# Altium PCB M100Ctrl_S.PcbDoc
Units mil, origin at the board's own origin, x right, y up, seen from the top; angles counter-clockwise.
Board outline 2362.2 x 2007.87 mil, 2 copper layers (Top Layer, Bottom Layer); 93 components, 74 nets, 370 pads, 105 vias.
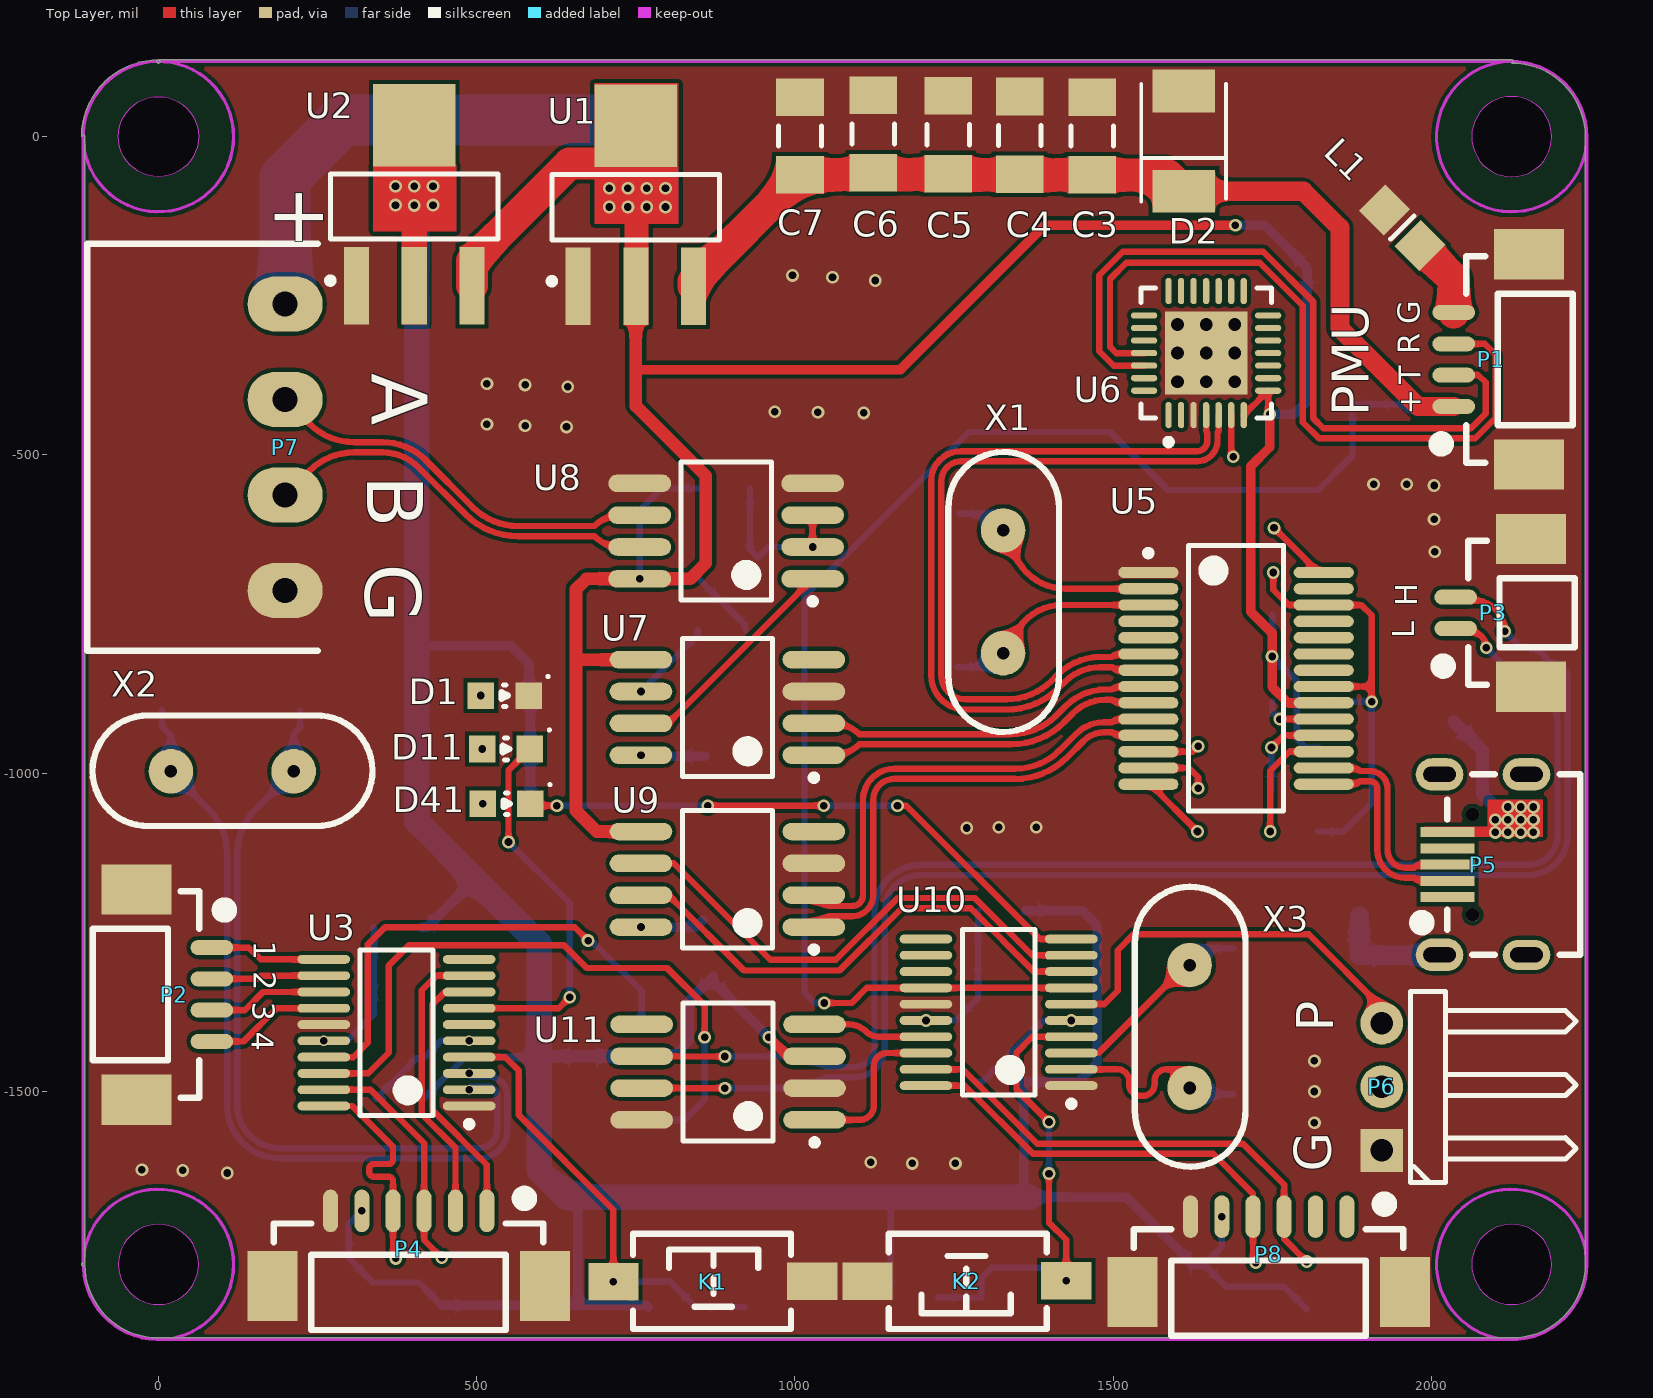
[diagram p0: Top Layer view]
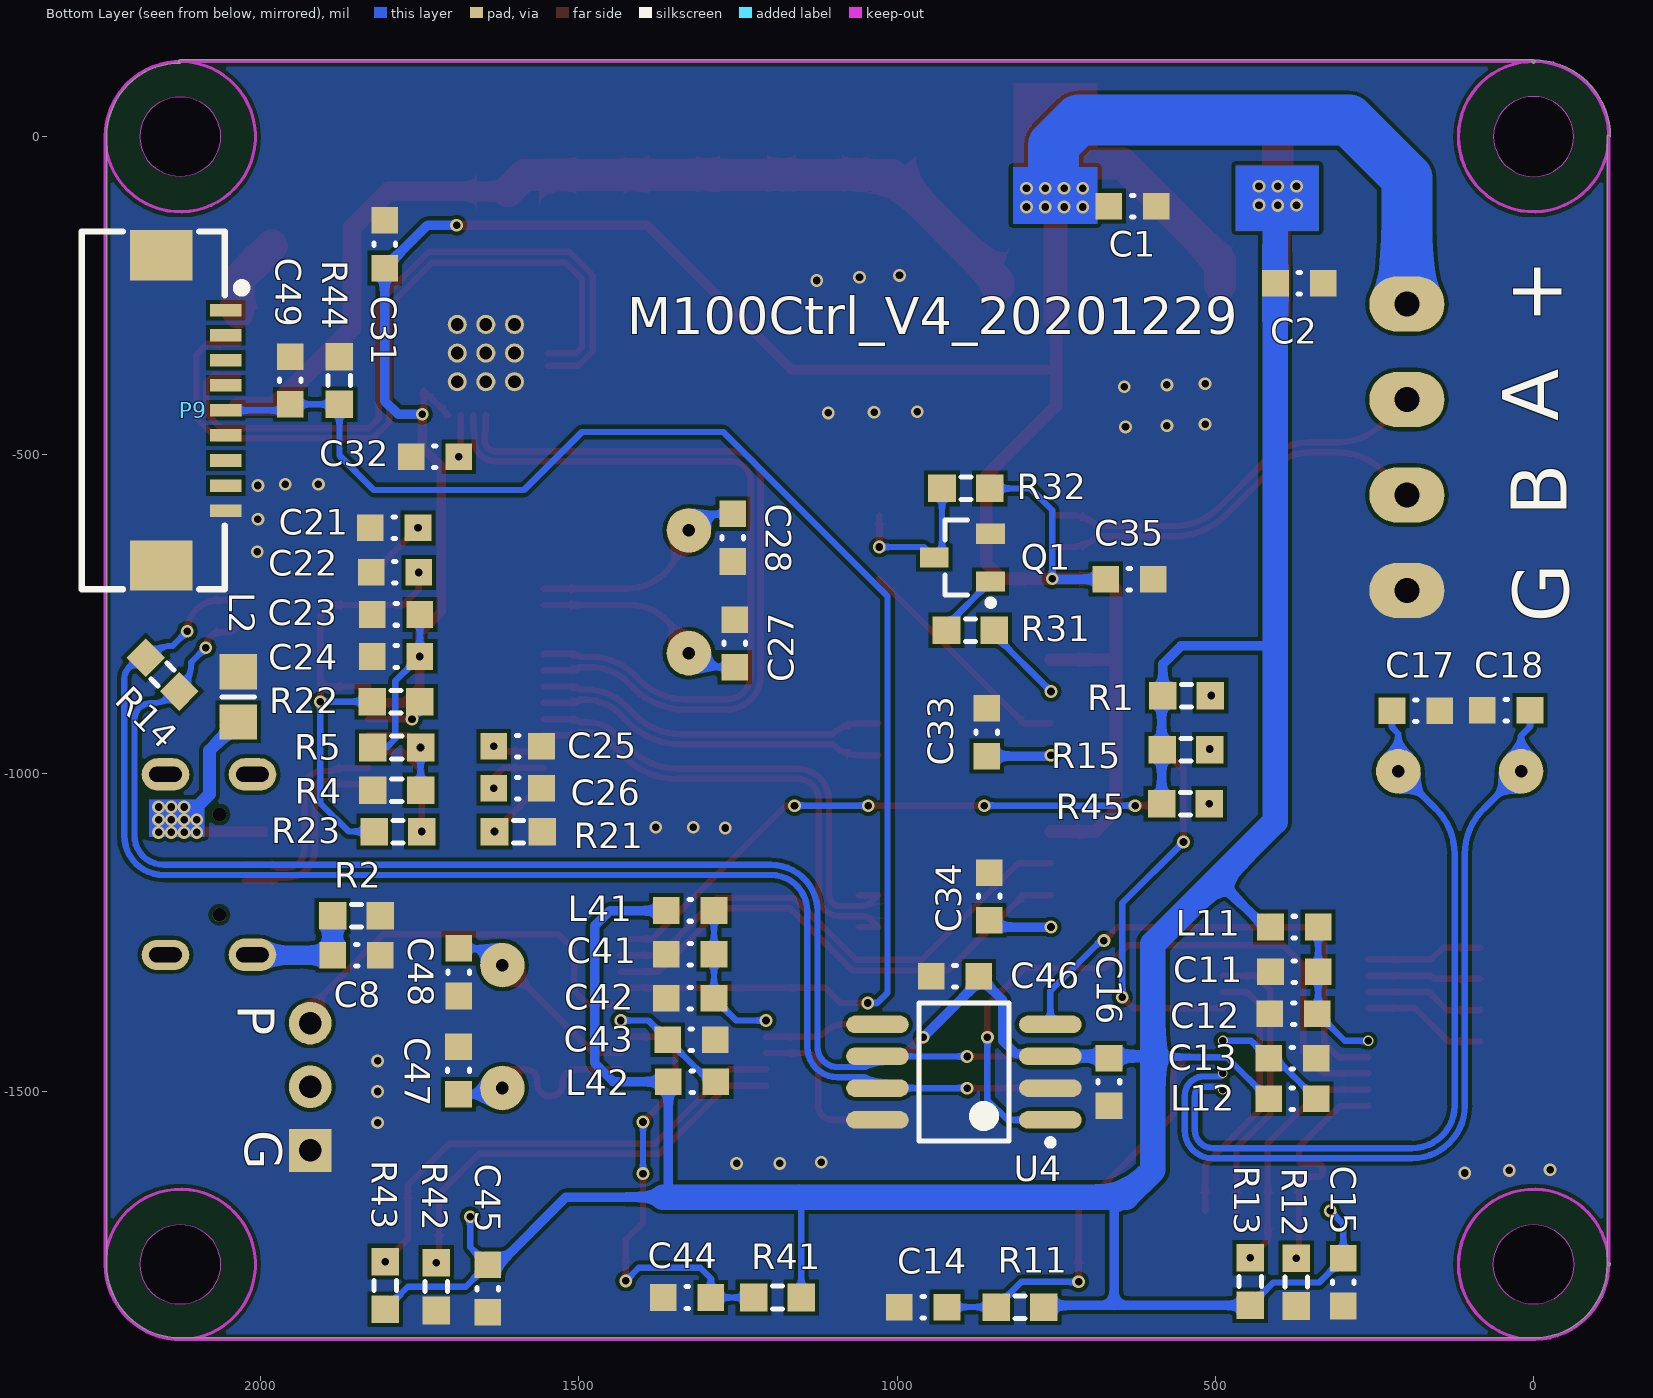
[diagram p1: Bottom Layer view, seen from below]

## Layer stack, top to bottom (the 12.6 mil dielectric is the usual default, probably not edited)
Top Solder: solder mask 0.4, Solder Resist, Dk 3.5
Top Layer: signal copper 1.4
Dielectric 1: dielectric 12.6, FR-4, Dk 4.8
Bottom Layer: signal copper 1.4
Bottom Solder: solder mask 0.4, Solder Resist, Dk 3.5

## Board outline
-120.63,-1771.68 cw(c0,-1771.65) -120.63,-1771.65 cw(c-118.11,-1771.65) -120.63,-1771.65 cw(c-118.11,-1771.65) -115.6,-1771.63 cw(c-118.11,-1771.65) -115.6,-1771.65 ccw(c0,-1771.65) -0.02,-1887.25 cw(c0,-1889.76) 0,-1887.25 2125.98,-1887.25 cw(c2125.98,-1889.76) 2126.01,-1887.25 ccw(c2125.98,-1771.65) 2241.58,-1771.65 2241.58,0 ccw(c2125.98,0) 2126.01,115.6 ccw(c2125.98,118.11) 2128.5,118.11 ccw(c2125.98,118.11) 2125.98,120.63 0,120.63 ccw(c0,118.11) -0.02,115.6 cw(c0,0) 0,115.6 ccw(c0,118.11) 2.52,118.11 ccw(c0,118.11) 0.02,120.63 ccw(c0,118.11) 0,120.63 ccw(c0,0) -120.63,0.02 cw(c-118.11,0) -115.6,0 -115.6,-1771.65 cw(c-118.11,-1771.65)
cut-out: 0,-62.99 cw(c0,0) -62.99,0 cw(c0,0) 0,62.99 cw(c0,0) 62.99,0 cw(c0,0)
cut-out: -62.99,-1771.65 ccw(c0,-1771.65) 0,-1834.65 ccw(c0,-1771.65) 62.99,-1771.65 ccw(c0,-1771.65) 0,-1708.66 ccw(c0,-1771.65)
cut-out: 2062.99,-1771.65 ccw(c2125.98,-1771.65) 2125.98,-1834.65 ccw(c2125.98,-1771.65) 2188.98,-1771.65 ccw(c2125.98,-1771.65) 2125.98,-1708.66 ccw(c2125.98,-1771.65)
cut-out: 2062.99,0 ccw(c2125.98,0) 2125.98,-62.99 ccw(c2125.98,0) 2188.98,0 ccw(c2125.98,0) 2125.98,62.99 ccw(c2125.98,0)

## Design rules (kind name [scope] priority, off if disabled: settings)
Clearance 24V [InNetClass('24V')] p1: gap=12
Clearance [All] p2: gap=6
ComponentClearance [All] p1: gap=0 collisioncheckmode=3 verticalgap=0 showdistances=FALSE
DiffPairsRouting [All] p1: maxlimit=10 minlimit=6 mostfreqgap=6 toplayer_minwidth=10 toplayer_maxwidth=10 toplayer_prefwidth=10 bottomlayer_minwidth=10 bottomlayer_maxwidth=10 bottomlayer_prefwidth=10 maxuncoupledlength=500
HoleSize [All] p1: absolutevalues=TRUE maxlimit=10000 minlimit=12 maxpercent=80.000 minpercent=20.000
HoleToHoleClearance [All] p1: gap=6 allowstackedmicrovias=TRUE
MinimumSolderMaskSliver [All] p1: minsoldermaskwidth=0
PolygonConnect VIA [OnLayer('Multi-Layer')] p1: connectstyle=Direct reliefconductorwidth=10 reliefentries=4 polygonreliefangle="90 Angle" airgapwidth=10
PolygonConnect [All] p2: connectstyle=Direct reliefconductorwidth=10 reliefentries=4 polygonreliefangle="90 Angle" airgapwidth=10
RoutingVias [All] p1: holewidth=12 width=15 viastyle="Through Hole" minholewidth=12 minwidth=12 maxholewidth=200 maxwidth=200
SilkToBoardRegionClearance [All] p1 off:
SilkToSilkClearance [All] p1: silktosilkclearance=0
SilkToSolderMaskClearance [IsPad] p1: minsilkscreentomaskgap=0 clearancetoexposedcopper=TRUE
SolderMaskExpansion [All] p1: expansion=4
Width [All] p1: maxlimit=10000 minlimit=6 preferedwidth=10
22 further rules are at their usual default settings.

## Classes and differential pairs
component class uart: C31 C32 C33 C34 C35 P6 P7 Q1 R31 R32 U6 U7 U8 U9
component class usbhub: C21 C22 C23 C24 C25 C26 C27 C28 L2 P5 R4 R5 R21 R22 R23 U5 X1
component class PWM2CAN: C11 C12 C13 C14 C15 C16 C17 C18 D11 K1 L11 L12 P2 P3 P4 R11 R12 R13 R14 R15 U3 U4 X2
component class power: C1 C2 C3 C4 C5 C6 C7 C8 D1 D2 L1 P1 R1 R2 U1 U2
component class rpm: C41 C42 C43 C44 C45 C46 C47 C48 C49 D41 K2 L41 L42 P8 P9 R41 R42 R43 R44 R45 U10 U11 X3
differential pair OSC_M1: +OSC_M1_P -OSC_M1_N
differential pair OSC_M2: +OSC_M2_P -OSC_M2_N
differential pair 485: +485_P -485_N
differential pair USB_MASTER: +USB_MASTER_P -USB_MASTER_N
differential pair USB4: +USB4_P -USB4_N
differential pair USB3: +USB3_P -USB3_N
differential pair USB2: +USB2_P -USB2_N
differential pair USB1: +USB1_P -USB1_N
differential pair OSC_HUB: +OSC_HUB_P -OSC_HUB_N
differential pair CAN: +CAN_P -CAN_N

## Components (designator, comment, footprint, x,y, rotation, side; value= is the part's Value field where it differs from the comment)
C1 "226" C0603/1608 630,-109 r0 bottom
C2 "226" C0603/1608 368,-230 r0 bottom
C3 "226" C1206/3216 1466.89,1 r270 top
C4 "226" C1206/3216 1352.89,2 r270 top
C5 "226" C1206/3216 1240.89,3 r270 top
C6 "226" C1206/3216 1122.89,4 r270 top
C7 "226" C1206/3216 1007.89,1 r270 top
C8 "104" C0603/1608 1849,-1286 r0 bottom
C11 "104" C0603/1608 375.89,-1311.65 r180 bottom
C12 "106" C0603/1608 376.89,-1377.65 r180 bottom
C13 "104" C0603/1608 378.89,-1447.65 r0 bottom
C14 "105" C0603/1608 958.89,-1838.65 r180 bottom
C15 "104" C0603/1608 298.89,-1799.65 r270 bottom
C16 "104" C0603/1608 667,-1485 r270 bottom
C17 "20pF" C0603/1608 185,-902 r180 bottom
C18 "20pF" C0603/1608 43,-901 r0 bottom
C21 "104" C0603/1608 1789.89,-614.65 r180 bottom
C22 "106" C0603/1608 1788.89,-684.65 r180 bottom
C23 "106" C0603/1608 1786.89,-750.65 r180 bottom
C24 "104" C0603/1608 1786.89,-816.65 r0 bottom
C25 "106" C0603/1608 1595.89,-957.65 r180 bottom
C26 "104" C0603/1608 1595.89,-1023.65 r180 bottom
C27 "20pF" C0603/1608 1254.89,-796 r90 bottom
C28 "20pF" C0603/1608 1257.89,-630 r270 bottom
C31 "105" C0603/1608 1804.89,-169 r270 bottom
C32 "104" C0603/1608 1725.89,-503 r180 bottom
C33 "104" C0603/1608 858.89,-935.65 r90 bottom
C34 "104" C0603/1608 854.89,-1193.65 r90 bottom
C35 "104" C0603/1608 634.89,-695 r0 bottom
C41 "104" C0603/1608 1324.89,-1284.65 r180 bottom
C42 "106" C0603/1608 1324.89,-1353.65 r180 bottom
C43 "104" C0603/1608 1322.89,-1418.65 r0 bottom
C44 "105" C0603/1608 1329.89,-1823.65 r180 bottom
C45 "104" C0603/1608 1642.89,-1809.65 r270 bottom
C46 "104" C0603/1608 908.89,-1319 r0 bottom
C47 "20pF" C0603/1608 1688.89,-1467 r90 bottom
C48 "20pF" C0603/1608 1688.34,-1312.6 r270 bottom
C49 "22nF" C0603/1608 1952.89,-383 r90 bottom
D1 "LED-红色" LED0603-蓝色 544,-878 r0 top
D2 "SMAJ11CA" DO-214AC/SMA 1611,-7 r270 top
D11 "LED-绿色" LED0603-蓝色 546,-962 r0 top
D41 "LED-蓝色" LED0603-蓝色 547,-1048 r0 top
K1 "KEY" 按键（2脚） 870.89,-1798.65 r0 top
K2 "KEY" 按键（2脚） 1270,-1798 r180 top
L1 "UPZ2012E221" L0805/2012 1954,-143 r315 top
L2 "UPZ2012E221" L0805/2012 2035,-880 r270 bottom
L11 "UPZ1608E101" L0603/1608 375.89,-1241.65 r180 bottom
L12 "UPZ1608E101" L0603/1608 378.89,-1511.65 r180 bottom
L41 "UPZ1608E101" L0603/1608 1324.89,-1215.65 r180 bottom
L42 "UPZ1608E101" L0603/1608 1321.89,-1484.65 r180 bottom
P1 "GH1.25-4P-N3API" GH1.25-4P（卧贴） 2034.89,-423.65 r270 top
P2 "GH1.25-4P" GH1.25-4P（卧贴） 83.89,-1274 r90 top
P3 "GH1.25-2P-CAN" GH1.25-2P（卧贴） 2037.89,-772.65 r270 top
P4 "GH1.25-6P-SW\UART\3.3V" GH1.25-6P（立贴） 515.89,-1687.65 r180 top
P5 "Micro USB" "Micro USB" 2080.89,-1143.65 r90 top
P6 "Header-3P" HDR2.54-WI-3P 1921.89,-1492.65 r90 top
P7 "KF-4P" KF3.81-4P（卧式） 199,-488 r270 top
P8 "GH1.25-6P-SW\UART\3.3V" GH1.25-6P（立贴） 1866.89,-1696.65 r180 top
P9 "SH1.0-9P-Realsense" FPC1.0-2H-WS-9P 2155.89,-430 r270 bottom
Q1 "PMBT3904" SOT-23-3 852.89,-698.65 r0 bottom
R1 "10k" R0603/1608 545,-878 r0 bottom
R2 "10k" R0603/1608 1849.34,-1224.27 r0 bottom
R4 "100k" R0603/1608 1785.89,-1026.65 r0 bottom
R5 "47k" R0603/1608 1785.89,-959.65 r180 bottom
R11 "1k" R0603/1608 806.89,-1839 r0 bottom
R12 "10k" R0603/1608 372.89,-1799.65 r90 bottom
R13 "10k" R0603/1608 444.89,-1798.65 r90 bottom
R14 "120R" R0603/1608 2153.89,-845 r45 bottom
R15 "10k" R0603/1608 546,-963 r0 bottom
R21 "2k7" R0603/1608 1594.89,-1091.65 r0 bottom
R22 "100k" R0603/1608 1786.89,-887.65 r180 bottom
R23 "100k" R0603/1608 1783.89,-1091.65 r180 bottom
R31 "4k7" R0603/1608 884.89,-775.65 r0 bottom
R32 "4k7" R0603/1608 891.89,-552.65 r0 bottom
R41 "1k" R0603/1608 1187.89,-1823.65 r0 bottom
R42 "10k" R0603/1608 1723.89,-1806.65 r90 bottom
R43 "10k" R0603/1608 1803.89,-1804.65 r90 bottom
R44 "20k" R0603/1608 1875.89,-383 r270 bottom
R45 "10k" R0603/1608 547,-1048 r0 bottom
U1 "AMS1117-5V" SOT-223 749.89,-109 r90 top
U2 "AMS1117-3.3V" SOT-223 401.89,-108 r90 top
U3 "STM32F042F4Px" TSSOP20 373.89,-1407.65 r180 top
U4 "SN65HVD230" SOP-8 894.89,-1469.65 r0 bottom
U5 "FE1.1S USB2.0 HUB" SOP65P780-28M 1692.89,-851 r0 top
U6 "CP2102" QFN50P500X500-28VAM 1645.89,-340 r90 top
U7 "CH340N" SOP-8 893.89,-896.65 r180 top
U8 "MAX485" SOP-8 891.89,-619.65 r180 top
U9 "CH340N" SOP-8 893.89,-1166.65 r180 top
U10 "STM32F042F4Px" TSSOP20 1319.89,-1375.65 r180 top
U11 "SN65HVD230" SOP-8 894.89,-1469.65 r180 top
X1 "XTAL" XTAL-49S 1327,-715 r270 top
X2 "XTAL" XTAL-49S 116,-997 r0 top
X3 "XTAL" XTAL-49S 1620,-1398 r270 top

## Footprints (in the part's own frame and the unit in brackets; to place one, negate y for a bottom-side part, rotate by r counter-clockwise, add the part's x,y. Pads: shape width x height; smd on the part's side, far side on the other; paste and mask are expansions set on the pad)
C0603/1608 [mm] "0603/1608贴片陶瓷电容"
  rect 1.06x1.06 smd: 1(-0.95,0) 2(0.95,0)
  silkscreen extent -0.05,-0.43 0.05,0.43, body extent -1.29,-0.48 1.31,0.53, height 0.95
C1206/3216 [mm] "1206/3216贴片陶瓷电容"
  rect 1.5x1.9 smd: 1(-1.55,0) 2(1.55,0)
  silkscreen extent -0.4,-0.85 0.4,0.85, body extent -2.18,-0.92 2.02,0.88, height 0.95
DO-214AC/SMA [mm]
  rect 1.7x2.5 smd: 1(-2,0) 2(2,0)
  silkscreen extent -2.29,-1.7 2.41,1.68, body extent -2.85,-1.25 2.85,1.25, height 1.9
FPC1.0-2H-WS-9P [mm] "翻盖FPC，脚距1mm，不含脚（长13.9mm，宽5.2mm，高1.96mm）"
  rect 2x2.5 smd: 0(-6.19,0) 0(6.19,0)
  rect 0.5x1.25 smd: 1(-4,2.575) 2(-3,2.575) 3(-2,2.575) 4(-1,2.575) 5(0,2.575) 6(1,2.575) 7(2,2.575) 8(3,2.575) 9(4,2.575)
  silkscreen extent -7.14,-3.18 7.14,3.31, body extent -6.95,-3.15 6.95,2.85, height 2
GH1.25-2P（卧贴） [mm]
  rect 2x2.8 smd: 0(-3.575,3) 0(2.325,3)
  oval 0.6x1.7 smd: 1(0,0) 2(-1.25,0)
  silkscreen extent -3.5,-0.75 2.25,4.75, body extent -4.45,-0.25 3.2,4.95, height 3.5
GH1.25-4P（卧贴） [mm]
  rect 2x2.8 smd: 0(-6.07,3) 0(2.325,3)
  oval 0.6x1.7 smd: 1(0,0) 2(-1.245,0) 3(-2.495,0) 4(-3.745,0)
  silkscreen extent -5.99,-0.75 2.26,4.75, body extent -6.95,-0.25 3.2,4.95, height 3.5
GH1.25-6P（立贴） [mm]
  rect 2x2.8 smd: 0(-2.325,3) 0(8.559,3)
  oval 0.6x1.7 smd: 1(0,0) 2(1.25,0) 3(2.5,0) 4(3.745,0) 5(4.989,0) 6(6.234,0)
  silkscreen extent -2.25,-0.75 8.5,4.75, body extent -3.21,0.15 9.44,4.35, height 4.7
HDR2.54-WI-3P [mm] "弯脚排针，3脚"
  rect 1.7x1.7 hole 0.9: 1(-2.54,0)
  round 1.7 hole 0.9: 2(0,0) 3(2.54,0)
  silkscreen extent -3.81,-7.76 3.81,-1.14, body extent -3.81,-7.77 3.81,1.27, height 4.85
KF3.81-4P（卧式） [mm]
  oval 2.2x3 hole 1: 1(-5.715,0) 2(-1.905,0) 3(1.905,0) 4(5.715,0)
  silkscreen extent -8.12,-7.9 8.12,1.3
L0603/1608 [mm] "0603/1608贴片磁珠"
  rect 1.06x1.06 smd: 1(-0.95,0) 2(0.95,0)
  silkscreen extent -0.05,-0.43 0.05,0.43, body extent -0.9,-0.5 0.9,0.5, height 1
L0805/2012 [mm] "0805/2012贴片磁珠"
  rect 1.4x1.5 smd: 1(-1,0) 2(1,0)
  silkscreen extent 0,-0.65 0,0.65, body extent -1.07,-0.7 1.08,0.7, height 0.7
LED0603-蓝色 [mm]
  rect 1.06x1.06 smd: 1(-0.95,0) 2(0.95,0)
  silkscreen extent -0.13,-0.43 1.78,0.81, body extent -0.8,-0.4 0.8,0.4, height 0.35
"Micro USB" [mm]
  oval 1.2x1.9 hole 0.6 slot 1.3 at 90 deg: 0(-3.6,-1.735)
  oval 1.3x1.9 hole 0.6 slot 1.3 at 90 deg: 0(-3.6,1.735) 0(3.6,-1.735) 0(3.6,1.735)
  rect 0.4x2.15 smd: 1(-1.3,1.425) 2(-0.65,1.425) 3(0,1.425) 4(0.65,1.425) 5(1.3,1.425)
  round 0.55 hole 0.55: FX(-2,0.415) FX(2,0.415)
  silkscreen extent -3.6,-3.88 3.6,2.69
QFN50P500X500-28VAM [mm] "28-Pin Plastic Quad Flat No-Lead 0.5 mm Pitch"
  oval 1.05x0.25 smd: 1(-2.475,1.5) 2(-2.475,1) 3(-2.475,0.5) 4(-2.475,0) 5(-2.475,-0.5) 6(-2.475,-1) 7(-2.475,-1.5) 15(2.475,-1.5) 16(2.475,-1) 17(2.475,-0.5) 18(2.475,0) 19(2.475,0.5) 20(2.475,1) 21(2.475,1.5)
  oval 0.25x1.05 smd: 8(-1.5,-2.475) 9(-1,-2.475) 10(-0.5,-2.475) 11(0,-2.475) 12(0.5,-2.475) 13(1,-2.475) 14(1.5,-2.475) 22(1.5,2.475) 23(1,2.475) 24(0.5,2.475) 25(0,2.475) 26(-0.5,2.475) 27(-1,2.475) 28(-1.5,2.475)
  round 0.762 hole 0.508: 29(-1.143,-1.143) 29(-1.143,0) 29(-1.143,1.143) 29(0,1.143) 29(0,0) 29(0,-1.143) 29(1.143,-1.143) 29(1.143,0) 29(1.143,1.143)
  rect 3.3x3.3 smd: 29(0,0)
  silkscreen extent -3.67,-2.6 2.6,2.6, body extent -2.58,-2.58 2.58,2.58, height 1
R0603/1608 [mm] "0603/1608贴片电阻"
  rect 1.1x1.1 smd: 1(-0.95,0) 2(0.95,0)
  silkscreen extent -0.2,-0.45 0.2,0.45, body extent -0.8,-0.4 0.8,0.4, height 0.45
SOP65P780-28M [mm]
  oval 2.4x0.45 smd: 1(-3.5,4.225) 2(-3.5,3.575) 3(-3.5,2.925) 4(-3.5,2.275) 5(-3.5,1.625) 6(-3.5,0.975) 7(-3.5,0.325) 8(-3.5,-0.325) 9(-3.5,-0.975) 10(-3.5,-1.625) 11(-3.5,-2.275) 12(-3.5,-2.925) 13(-3.5,-3.575) 14(-3.5,-4.225) 15(3.5,-4.225) 16(3.5,-3.575) 17(3.5,-2.925) 18(3.5,-2.275) 19(3.5,-1.625) 20(3.5,-0.975) 21(3.5,-0.325) 22(3.5,0.325) 23(3.5,0.975) 24(3.5,1.625) 25(3.5,2.275) 26(3.5,2.925) 27(3.5,3.575) 28(3.5,4.225)
  silkscreen extent -3.62,-5.3 1.9,5.3, body extent -2.7,-5.3 2.7,5.3, height 2
SOP-8 [mm]
  oval 2.5x0.7 smd: 1(-3.45,1.905) 2(-3.45,0.635) 3(-3.45,-0.635) 4(-3.45,-1.905) 5(3.45,-1.905) 6(3.45,-0.635) 7(3.45,0.635) 8(3.45,1.905)
  silkscreen extent -3.57,-2.75 1.8,2.93, body extent -2.73,-2.75 2.73,2.75, height 2.13
SOT-23-3 [mm]
  rect 1.15x0.8 smd: 1(0,0) 2(0,-1.9) 3(2.25,-0.95)
  silkscreen extent -0.12,-2.45 1.83,0.97, body extent -0.38,-2.5 2.62,0.6, height 1.1
SOT-223 [mm]
  rect 3.1x1 smd: 1(-3.2,2.3) 2(-3.2,0) 3(-3.2,-2.3)
  rect 3.3x3.3 smd: 4(3.2,0)
  silkscreen extent -3.12,-3.35 1.25,3.47, body extent -1.9,-3.35 1.8,3.35, height 1.8
TSSOP20 [mm]
  oval 2.1x0.35 smd: 1(-2.9,2.925) 2(-2.9,2.275) 3(-2.9,1.625) 4(-2.9,0.975) 5(-2.9,0.325) 6(-2.9,-0.325) 7(-2.9,-0.975) 8(-2.9,-1.625) 9(-2.9,-2.275) 10(-2.9,-2.925) 11(2.9,-2.925) 12(2.9,-2.275) 13(2.9,-1.625) 14(2.9,-0.975) 15(2.9,-0.325) 16(2.9,0.325) 17(2.9,0.975) 18(2.9,1.625) 19(2.9,2.275) 20(2.9,2.925)
  silkscreen extent -3.03,-3.3 1.45,3.77, body extent -2.25,-3.3 2.25,3.3, height 1.2
XTAL-49S [mil]
  round 70 hole 20: 1(-96.5,0) 2(96.5,0)
  silkscreen extent -220,-86 220,88, body extent -224,-92 223,92, height 142
按键（2脚） [mm]
  rect 2x1.5 smd: 1(-3.966,-0.01) 2(3.966,0.01)
  silkscreen extent -3.18,-1.89 3.12,1.91, body extent -3.97,-1.87 4.03,1.63, height 2.59

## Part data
C1 C2 C3 C4 C5 C6 C7 C8 C11 C12 C13 C14 C15 C16 C17 C18 C21 C22 C23 C24 C25 C26 C27 C28 C31 C32 C33 C34 C35 C41 C42 C43 C44 C45 C46 C47 C48 C49: library part 陶瓷电容, "陶瓷电容"
D1 D11 D41: library part LED, "发光二极管"
D2: library part 瞬态抑制二极管, "瞬态抑制二极管"
K1 K2: library part 按键（2脚）, "按键-2脚贴片"
L1 L2 L11 L12 L41 L42: library part 磁珠, "贴片磁珠"
P2: "GH1.25-4P-CAN\5V"
P5: "Micro USB底座"
Q1: library part NPN, "NPN三极管"
R1 R2 R4 R5 R11 R12 R13 R14 R15 R21 R22 R23 R31 R32 R41 R42 R43 R44 R45: library part 电阻, "电阻"
U1 U2: library part AMS1117, "AMS1117低压差线性稳压器"
U4 U11: "CAN收发芯片"
U7 U9: "USB-TTL转换芯片"
X1 X2 X3: library part 晶振, "晶振"

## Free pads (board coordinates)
  round 216.54 on Top Solder: ""(0,-1771.65) ""(0,0) ""(2125.98,-1771.65) ""(2125.98,0)
  round 216.54 on Bottom Solder: ""(0,-1771.65) ""(0,0) ""(2125.98,-1771.65) ""(2125.98,0)

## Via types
v1: diameter 20, hole 12, Top Layer to Bottom Layer, tented both sides, 101 vias
v2: diameter 15, hole 12, Top Layer to Bottom Layer, tented both sides, 2 vias
v3: diameter 16, hole 12, Top Layer to Bottom Layer, tented both sides, 2 vias

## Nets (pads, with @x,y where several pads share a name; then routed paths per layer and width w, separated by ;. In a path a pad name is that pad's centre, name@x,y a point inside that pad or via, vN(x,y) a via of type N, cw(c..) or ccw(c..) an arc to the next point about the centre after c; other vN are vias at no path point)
485_N: P7.3 U8.7 | length 631.2
  Top Layer w10: P7.3 236.71,-525.29 cw(c307.42,-596) 307.42,-496 352,-496 cw(c352,-575.67) 408.33,-519.33 482.68,-593.68 ccw(c564.7,-511.65) 564.7,-627.65 684.85,-627.65 ccw(c725.89,-586.61) 725.89,-644.65 U8.7
485_P: P7.2 U8.6 | length 631.2
  Top Layer w10: P7.2 236.71,-450.71 ccw(c307.42,-380) 307.42,-480 352,-480 cw(c352,-575.67) 419.65,-508.02 493.99,-582.36 ccw(c564.7,-511.65) 564.7,-611.65 684.85,-611.65 cw(c725.89,-652.7) 725.89,-594.65 U8.6
CAN_N: P3.1 R14.1 U4.6 U11.6 | length 2163.7
  Top Layer w10: U11.6 813.28,-1444.65 813.62,-1445 v1(889.89,-1445) ; P3.1 ccw(c2049.96,-760.58) 2049.96,-777.65 2060.54,-777.65 cw(c2060.54,-803) v1(2085.89,-803)
  Bottom Layer w10: v1(889.89,-1445) 976.16,-1445 976.5,-1444.65 U4.6 1043.35,-1457.29 ccw(c1053.89,-1446.75) 1053.89,-1461.65 1093.24,-1461.65 ccw(c1093.24,-1430) 1124.89,-1430 1124.89,-1217 cw(c1197.89,-1217) 1197.89,-1144 2151.89,-1144 ccw(c2151.89,-1098) 2197.89,-1098 2197.89,-915.24 ccw(c2172.94,-915.24) 2172.94,-890.29 cw(c2172.94,-825.95) R14.1 cw(c2172.94,-825.95) 2108.6,-825.95 2108.6,-825.71 v1(2085.89,-803)
CAN_P: P3.2 R14.2 U4.7 U11.7 | length 2254.5
  Top Layer w10: U11.7 889.54,-1494.65 v1(889.89,-1495) ; P3.2 ccw(c2049.96,-711.37) 2049.96,-728.44 2066.33,-728.44 cw(c2066.33,-777) v1(2114.89,-777)
  Bottom Layer w10: v1(889.89,-1495) 890.24,-1494.65 U4.7 1043.35,-1482.02 cw(c1053.89,-1492.56) 1053.89,-1477.65 1093.24,-1477.65 ccw(c1093.24,-1430) 1140.89,-1430 1140.89,-1217 cw(c1197.89,-1217) 1197.89,-1160 2151.89,-1160 ccw(c2151.89,-1098) 2213.89,-1098 2213.89,-852.11 ccw(c2187.41,-852.11) 2187.41,-825.62 cw(c2187.41,-818.55) R14.2 2178.39,-816.6 ccw(c2137.6,-857.39) 2137.6,-799.71 v1(2114.89,-777)
CH340_RXD: U7.7 U8.1 | length 363.7
  Top Layer w10: U7.7 800.72,-921.65 U8.1
CH340_TXD: R31.1 U7.6 | length 133
  Bottom Layer w10: v1(758.06,-871.65) 847.49,-782.23 R31.1
CP2102_RXD: P1.3 U6.25 | length 1187.5
  Top Layer w10: U6.25 1504.89,-340 1494.89,-330 1494.89,-223.63 1520.52,-198 1730.26,-198 1797.89,-265.63 1797.89,-448.63 1823.26,-474 2068.52,-474 2100.89,-441.63 2100.89,-343 2083.33,-325.44 P1.3
CP2102_TXD: P1.2 U6.26 | length 1156.4
  Top Layer w10: U6.26 1500.57,-359.69 1477.89,-337 1477.89,-218 1514.89,-181 1735.89,-181 1813.89,-259 1813.89,-442 1829.89,-458 2061.89,-458 2084.89,-435 2084.89,-386 2073.54,-374.65 P1.2
FE_3V3: C22.2 R22.1 R23.1 U5.21 U5.26 | length 753
  Top Layer w10: v1(1751.49,-684.65) 1751.49,-711.6 1775.73,-735.84 U5.26 1889.73,-735.84 1905.89,-752 1905.89,-863.8 ; U5.21 1905.89,-863.8 ; v1(1905.89,-887.65) 1905.89,-863.8
  Bottom Layer w10: R23.1 1861.24,-1091.65 1905.89,-1047 v1(1905.89,-887.65) R22.1
GND: C1.1 C2.1 C3.1 C4.1 C5.1 C6.1 C7.1 C8.1 C11.1 C12.1 C13.1 C14.1 C15.2 C16.2 C17.2 C18.2 C21.1 C22.1 C23.1 C24.2 C25.2 C26.2 C27.2 C28.2 C31.1 C32.1 C33.2 C34.2 C35.1 C41.1 C42.1 C43.1 C44.1 C45.2 C46.2 C47.2 C48.2 C49.2 D1.2 D2.1 K1.2 K2.2 L1.1 L2.1 P1.0 P2.0 P3.0 P4.0 P4.6 P6.1 P7.4 P8.0 P8.6 P9.0 P9.9 Q1.2 R2.1 R4.2 R12.1 R21.1 R42.1 R44.1 U1.1 U2.1 U3.1 U3.15 U4.2 U4.8 U5.1 U6.3 U6.29 U7.3 U8.4 U8.5 U9.3 U10.1 U10.15 U11.2 U11.8
  other v1: 108,-1628 38,-1624 -26,-1623 1184,-1613 1252,-1613 1119,-1611 1816,-1549 1816,-1500 1816,-1452 1270,-1086 1320,-1085 1379,-1085 2005,-652 2004,-601 2004,-548 1909,-546 1961,-546 641,-456 576,-454 516,-452 1108,-434 1036,-433 968,-432 643,-393 576,-390 516,-388 1126,-226 1059,-221 996,-218
LED1: D11.2 U3.7 | length 608.7
  Top Layer w10: U3.7 628.73,-1369.27 v1(646,-1352) ; v1(550,-1108) 550,-995.4 D11.2
  Bottom Layer w10: v1(550,-1108) 646,-1204 v1(646,-1352)
LED2: D41.2 U10.10 | length 937.7
  Top Layer w10: D41.2 587.4,-1051 v1(626,-1051) ; v1(863,-1051) v1(1045,-1051) ; v1(1161,-1051) 1175,-1051 1384.5,-1260.5 U10.10
  Bottom Layer w10: v1(626,-1051) v1(863,-1051) ; v1(1045,-1051) v1(1161,-1051)
M1_CAN_RX: U3.17 U4.4 | length 768.1
  Top Layer w10: U3.17 305.96,-1446.04 329,-1423 329,-1269 356,-1242 654,-1242 v1(675,-1263)
  Bottom Layer w10: v1(675,-1263) 680,-1263 759.06,-1342.06 U4.4
M1_CAN_TX: U3.18 U4.1 | length 1061.5
  Top Layer w10: U3.18 329.37,-1471.63 362,-1439 362,-1302 394,-1270 637,-1270 673,-1306 799,-1306 858,-1365 v1(858,-1415)
  Bottom Layer w10: U4.1 826.35,-1544.65 858,-1513 v1(858,-1415)
M1_NRST: C14.2 K1.1 R11.2 U3.4 | length 703.7
  Top Layer w10: U3.4 544.93,-1446.04 565.89,-1467 565.89,-1537 714.73,-1685.84 v1(714.73,-1799.05)
  Bottom Layer w10: v1(714.73,-1799.05) 804.34,-1799.05 R11.2 844.64,-1838.65 C14.2
M1_SWCLK: P4.4 R12.2 U3.20 | length 375.2
  Top Layer w10: U3.20 304.7,-1522.81 368.46,-1586.57 368.46,-1607 cw(c361.46,-1607) 361.46,-1614 338.19,-1614 ccw(c338.19,-1621) 331.19,-1621 331.19,-1627 ccw(c338.19,-1627) 338.19,-1634 361.46,-1634 cw(c361.46,-1641) 368.46,-1641 368.46,-1644 P4.4 368.46,-1757.83 v1(372.89,-1762.25)
M1_SWDIO: P4.3 R13.2 U3.19 | length 383.7
  Top Layer w10: U3.19 333.11,-1497.22 417.46,-1581.57 P4.3 417.46,-1733.83 v1(444.89,-1761.25)
M1_USART2_RX: P4.2 U3.9 | length 452.2
  Top Layer w10: P4.2 466.68,-1588.41 413.89,-1535.63 413.89,-1341 436.8,-1318.09 U3.9
M1_USART2_TX: P4.1 U3.8 | length 425.9
  Top Layer w10: U3.8 450.21,-1343.68 429.89,-1364 429.89,-1529 515.89,-1615 P4.1
M2_CAN_RX: U10.17 U11.4 | length 180.2
  Top Layer w10: U11.4 1084.5,-1394.65 cw(c1084.5,-1433.39) 1111.89,-1406 ccw(c1131.3,-1386.59) 1131.3,-1414.04 U10.17
M2_CAN_TX: U10.18 U11.1 | length 261.6
  Top Layer w10: U11.1 1101.24,-1544.65 ccw(c1101.24,-1522) 1123.89,-1522 1123.89,-1460 cw(c1144.26,-1460) 1144.26,-1439.63 U10.18
M2_NRST: C44.2 K2.1 R41.2 U10.4 | length 733.8
  Top Layer w10: v1(1399,-1629) 1399,-1706 1426.16,-1733.16 v1(1426.16,-1797.61) ; v1(1399,-1548) 1348,-1497 1348,-1439 1372.96,-1414.04 U10.4
  Bottom Layer w10: R41.2 C44.2 1292.49,-1793.51 1309,-1777 1405.55,-1777 v1(1426.16,-1797.61) ; v1(1399,-1629) v1(1399,-1548)
M2_SWCLK: P8.4 R42.2 U10.20 | length 694.6
  Top Layer w10: U10.20 1266.7,-1490.81 1373.89,-1598 1656.89,-1598 1719.46,-1660.57 P8.4 1719.46,-1764.83 v1(1723.89,-1769.25)
M2_SWDIO: P8.3 R43.2 U10.19 | length 773.2
  Top Layer w10: U10.19 1263.74,-1465.22 1380.52,-1582 1703.89,-1582 1768.46,-1646.57 P8.3 1768.46,-1731.83 v1(1803.89,-1767.25)
M2_USART2_RX: U9.6 U10.9 | length 816.2
  Top Layer w10: U9.6 809.54,-1141.65 960.89,-1293 1064.26,-1293 1161.26,-1196 1282.52,-1196 1372.6,-1286.09 U10.9
M2_USART2_TX: U9.7 U10.8 | length 806.9
  Top Layer w10: U9.7 801.54,-1191.65 919.89,-1310 1069.89,-1310 1167.89,-1212 1275.89,-1212 1375.57,-1311.68 U10.8
N3-M1: P2.1 U3.11 | length 183.5
  Top Layer w10: P2.1 142,-1274 160.5,-1292.5 U3.11
N3-M2: P2.2 U3.12 | length 177.9
  Top Layer w10: P2.2 156,-1323 160.91,-1318.09 U3.12
N3-M3: P2.3 U3.13 | length 187.6
  Top Layer w10: P2.3 135.79,-1372.21 164.32,-1343.68 U3.13
N3-M4: P2.4 U3.14 | length 197.4
  Top Layer w10: P2.4 133.57,-1421.43 185.73,-1369.27 U3.14
N3_9V: C3.2 C4.2 C5.2 C6.2 C7.2 D2.2 P1.1 U1.3 | length 1514.5
  Top Layer w30: D2.2 1798.63,-85.74 1855.89,-143 1855.89,-301 1978.54,-423.65 P1.1
  Top Layer w50: U1.3 840.44,-227.47 C7.2 C3.2 1585.28,-60.02 D2.2
N3_PPS: P6.3 U10.6 | length 643.1
  Top Layer w10: U10.6 1486.03,-1362.86 1506.89,-1342 1506.89,-1278 1531.89,-1253 1806.89,-1253 1921.89,-1368 P6.3
NetC11_2: C11.2 C12.2 L11.2 U3.16 | length 233.9
  Bottom Layer w10: v3(259.72,-1420.45) 296.69,-1420.45 C12.2 338.49,-1376.65 C11.2 L11.2
NetC13_2: C13.2 L12.2 U3.5 | length 195.2
  Bottom Layer w10: L12.2@352.29,-1511.65 L12.2 405.49,-1447.65 C13.2 443.5,-1420.45 v3(488.06,-1420.45)
NetC21_2: C21.2 U5.28 | length 90.9
  Top Layer w10: v1(1752.49,-614.65) 1814.5,-676.66 U5.28@1817.69,-676.66
NetC25_1: C25.1 U5.12 | length 81
  Top Layer w10: U5.12 1624.79,-966.16 v1@1632.79,-958.16
  other v1: 1633.29,-957.65
NetC26_1: C26.1 U5.13 | length 101.6
  Top Layer w10: U5.13 1618.75,-991.75 1633.29,-1006.29 v1(1633.29,-1023.65)
NetC32_2: C32.2 U6.6 | length 66.9
  Top Layer w10: U6.6 1685.26,-499.77 v1(1688.49,-503)
NetC33_1: C33.1 U7.8 | length 101.4
  Bottom Layer w15: v1(758.06,-971.65) 759.46,-973.06 C33.1
NetC34_1: C34.1 U9.8 | length 101.2
  Bottom Layer w15: v1(758.06,-1241.65) 844.29,-1241.65 C34.1
NetC41_2: C41.2 C42.2 L41.2 U10.16 | length 234.2
  Bottom Layer w10: v1(1205.72,-1388.45) 1252.69,-1388.45 C42.2 C41.2 L41.2
NetC43_2: C43.2 L42.2 U10.5 | length 189.4
  Bottom Layer w10: L42.2 1294.29,-1484.65 C43.2 1390.5,-1388.45 v1(1434.06,-1388.45)
NetD1_1: D1.1 R1.1
  other v1: 506.6,-878
NetD11_1: D11.1 R15.1
  other v1: 508.6,-962
NetD41_1: D41.1 R45.1
  other v1: 509.6,-1048
NetL1_2: L1.2 P1.4 | length 127.4
  Top Layer w50: L1.2 2034.89,-223.89 P1.4
NetL2_2: L2.2 P5.5 | length 176.1
  Bottom Layer w20: L2.2 2080,-964.37 2080,-1033 2111,-1064
  other v1: 2100,-1093 2120,-1093 2140,-1093 2160,-1093 2100,-1073 2120,-1073 2140,-1073 2160,-1073 2120,-1053 2140,-1053 2160,-1053
NetQ1_1: Q1.1 R31.2 | length 105.7
  Bottom Layer w10: Q1.1 922.29,-768.06 R31.2
NetQ1_3: Q1.3 R32.2 U8.2 U8.3 | length 256.8
  Top Layer w10: v1(1027.72,-644.65) U8.3
  Bottom Layer w10: R32.2 929.29,-649.07 Q1.3 958.07,-644.65 v1(1027.72,-644.65)
NetR4_1: R4.1 R5.2 U5.18 | length 157.1
  Top Layer w10: v1(1748.49,-959.65) 1767.57,-940.57 U5.18
  Bottom Layer w10: R4.1 v1(1748.49,-959.65)
NetR21_2: R21.2 U5.14 | length 108
  Top Layer w10: U5.14 1557.98,-1017.34 v1(1632.29,-1091.65)
NetR22_2: R22.2 U5.19 | length 101.2
  Top Layer w10: v1(1762,-915) U5.19
  Bottom Layer w10: R22.2 1749.49,-902.49 v1(1762,-915)
NetR23_2: R23.2 U5.17 | length 192
  Top Layer w10: v1(1746.49,-1091.65) 1746.49,-996.4 1776.73,-966.16 U5.17
OSC_HUB_N: C28.1 U5.2 X1.1 | length 364.4
  Top Layer w10: X1.1@1338.89,-624 ccw(c1425.14,-624) 1425.14,-710.25 U5.2
  Bottom Layer w10: C28.1 1307.49,-592.6 cw(c1307.49,-624) X1.1@1338.89,-624
OSC_HUB_P: C27.1 U5.3 X1.2 | length 355.9
  Top Layer w10: X1.2@1338.89,-816.13 cw(c1419.17,-816.13) 1419.17,-735.84 U5.3
  Bottom Layer w10: C27.1 1321.61,-833.4 ccw(c1321.61,-816.13) X1.2@1338.89,-816.13
OSC_M1_N: C18.1 U3.3 X2.1 | length 1306
  Bottom Layer w10: C18.1 5.6,-926.87 19.5,-940.77 X2.1 78.71,-1056.21 cw(c8,-1126.92) 108,-1126.92 108,-1522 ccw(c191,-1522) 191,-1605 504,-1605 ccw(c504,-1561) 548,-1561 548,-1506.43 ccw(c518,-1506.43) 518,-1476.43 492.86,-1476.43 cw(c492.86,-1471.63) v2(488.06,-1471.63)
OSC_M1_P: C17.1 U3.2 X2.2 | length 1227.9
  Bottom Layer w10: C17.1 222.4,-927.87 212.5,-937.77 X2.2 153.29,-1056.21 ccw(c224,-1126.92) 124,-1126.92 124,-1522 ccw(c191,-1522) 191,-1589 504,-1589 ccw(c504,-1561) 532,-1561 532,-1506.43 ccw(c518,-1506.43) 518,-1492.43 492.86,-1492.43 ccw(c492.86,-1497.22) v2(488.06,-1497.22)
OSC_M2_N: C48.1 U10.3 X3.1 | length 322.4
  Top Layer w10: U10.3 1476.79,-1439.63 X3.1@1622.89,-1293.53
  Bottom Layer w10: X3.1@1622.89,-1293.53 1641.22,-1275.2 C48.1
OSC_M2_P: C47.1 U10.2 X3.2 | length 323.1
  Top Layer w10: U10.2 1505.89,-1465.22 1506.89,-1465.22 cw(c1506.89,-1483.22) 1524.89,-1483.22 1524.89,-1488.7 ccw(c1542.89,-1488.7) 1542.89,-1506.7 1546.89,-1506.7 ccw(c1546.89,-1488.7) 1564.89,-1488.7 1564.89,-1483.22 cw(c1582.89,-1483.22) 1582.89,-1465.22 1584.89,-1465.22 1602.46,-1465.22 X3.2@1622.89,-1485.65
  Bottom Layer w10: X3.2@1622.89,-1485.65 1641.64,-1504.4 C47.1
RS_PULSE: C49.1 P9.5 R44.2 U10.7 U10.14 | length 2349.7
  Top Layer w10: v1(1045.89,-1361) 1088.89,-1361 1112.62,-1337.27 U10.14 U10.7
  Bottom Layer w10: v1(1045.89,-1361) 1030.89,-1361 1014.89,-1345 1014.89,-722.11 1273,-464 1494.89,-464 1585.89,-555 1821.89,-555 1875.89,-501 R44.2 C49.1 1962.49,-430 P9.5
USB1_N: U5.10 U9.2 | length 773.5
  Top Layer w10: U9.2@1059.89,-1191.65 U9.2 1039.52,-1201.46 ccw(c1056.89,-1184.09) 1056.89,-1208.65 1089.89,-1208.65 ccw(c1089.89,-1191.65) 1106.89,-1191.65 1106.89,-1042 cw(c1155.89,-1042) 1155.89,-993 1345.47,-993 ccw(c1345.47,-893) 1416.18,-963.71 1441.89,-937.99 cw(c1485.89,-981.99) 1485.89,-919.77 1498.06,-919.77 cw(c1509.63,-931.35) 1509.63,-914.98 U5.10
USB1_P: U5.11 U9.1 | length 773.5
  Top Layer w10: U9.1@1059.89,-1241.65 U9.1 1039.52,-1231.85 cw(c1056.89,-1249.21) 1056.89,-1224.65 1089.89,-1224.65 ccw(c1089.89,-1191.65) 1122.89,-1191.65 1122.89,-1042 cw(c1155.89,-1042) 1155.89,-1009 1345.47,-1009 ccw(c1345.47,-893) 1427.49,-975.02 1453.21,-949.31 cw(c1485.89,-981.99) 1485.89,-935.77 1498.06,-935.77 ccw(c1509.63,-924.19) 1509.63,-940.57 U5.11
USB2_N: U5.8 U7.2 | length 552.1
  Top Layer w10: U7.2 1059.89,-921.65 cw(c1059.89,-979.7) 1100.93,-938.65 1339.81,-938.65 ccw(c1339.81,-838.65) 1410.53,-909.36 1425.43,-894.46 cw(c1487.89,-956.93) 1487.89,-868.59 1498.06,-868.59 cw(c1509.63,-880.17) 1509.63,-863.8 U5.8
USB2_P: U5.9 U7.1 | length 552.1
  Top Layer w10: U7.1 1059.89,-971.65 ccw(c1059.89,-913.61) 1100.93,-954.65 1339.81,-954.65 ccw(c1339.81,-838.65) 1421.84,-920.68 1436.74,-905.78 cw(c1487.89,-956.93) 1487.89,-884.59 1498.06,-884.59 ccw(c1509.63,-873.01) 1509.63,-889.39 U5.9
USB3_N: U5.6 U6.5 | length 1183.3
  Top Layer w10: U5.6 1509.63,-812.61 ccw(c1509.63,-828.99) 1498.06,-817.41 1479.5,-817.41 ccw(c1479.5,-911.61) 1412.9,-844.99 1403.18,-854.71 cw(c1332.47,-784) 1332.47,-884 1267.89,-884 cw(c1267.89,-846) 1229.89,-846 1229.89,-541 cw(c1260.89,-541) 1260.89,-510 1631.73,-510 ccw(c1631.73,-478) 1663.73,-478 1663.73,-464.95 ccw(c1659.28,-460.5) 1665.57,-460.5 U6.5
USB3_P: U5.7 U6.4 | length 1208.4
  Top Layer w10: U5.7 1509.63,-838.2 cw(c1509.63,-821.83) 1498.06,-833.41 1479.5,-833.41 ccw(c1479.5,-911.61) 1424.2,-856.31 1414.49,-866.02 cw(c1332.47,-784) 1332.47,-900 1267.89,-900 cw(c1267.89,-846) 1213.89,-846 1213.89,-541 cw(c1260.89,-541) 1260.89,-494 1631.73,-494 ccw(c1631.73,-478) 1647.73,-478 1647.73,-464.95 cw(c1652.18,-460.5) 1645.89,-460.5 U6.4
USB4_N: U5.4
USB4_P: U5.5
USB_5V: P5.1
USB_MASTER_N: P5.2 U5.15 | length 324.5
  Top Layer w10: U5.15 1876.15,-1017.34 ccw(c1876.15,-1000.97) 1887.72,-1012.54 1902.89,-1012.54 cw(c1902.89,-1024.54) 1914.89,-1024.54 1914.89,-1120.45 ccw(c1958.89,-1120.45) 1958.89,-1164.45 1972.67,-1164.45 ccw(c1984.25,-1152.87) 1984.25,-1169.24 P5.2
USB_MASTER_P: P5.3 U5.16 | length 324.5
  Top Layer w10: U5.16 1876.15,-991.75 cw(c1876.15,-1008.12) 1887.72,-996.54 1902.89,-996.54 cw(c1902.89,-1024.54) 1930.89,-1024.54 1930.89,-1120.45 ccw(c1958.89,-1120.45) 1958.89,-1148.45 1972.67,-1148.45 cw(c1984.25,-1160.03) 1984.25,-1143.65 P5.3
USB_SHELL: C8.2 P5.0@2012.58,-1285.39 R2.2 | length 188.3
  Bottom Layer w30: R2.2 1886.74,-1285.66 C8.2 2011.97,-1286 P5.0@2012.58,-1285.39
VCC_3V3: C2.2 C15.1 C16.1 C45.1 C46.1 L11.1 L12.1 L41.1 L42.1 P4.5 P8.5 R1.2 R11.1 R13.1 R15.2 R41.1 R43.1 R45.2 U2.2 U2.4 U4.3 U11.3 | length 5975.1
  Top Layer w15: v1(959,-1415) 988.65,-1444.65 U11.3
  Top Layer w50: v1(401.89,-108) v1(401.89,-78) U2.4
  Bottom Layer w10: v1(319.46,-1687.65) 298.89,-1708.23 C15.1 336.64,-1800 408.83,-1800 R13.1 ; L12.1 481.94,-1446 598,-1446 ; R41.1 1150.49,-1668.51 1153,-1666 ; v1(1670.46,-1696.65) 1670.46,-1744.68 C45.1 1677.64,-1807 1768.83,-1807 R43.1
  Bottom Layer w15: 406,-803 409,-800 554,-800 582.4,-828.4 R1.2 584.4,-880 R45.2 ; L11.1 422.35,-1241.65 497,-1167 ; R13.1 659,-1836.06 ; 640,-1666 659,-1685 659,-1836.06 ; U4.3 755.01,-1440.6 813.4,-1440.6 834,-1420 834,-1356.49 C46.1 871.49,-1327.49 v1(959,-1415) ; R11.1 766.54,-1836.06 659,-1836.06 ; 842,-1665 843,-1666 ; L41.1 1362.64,-1216 1451,-1216 1475,-1240 1475,-1455 1445.35,-1484.65 L42.1 1359.29,-1657.29 1368,-1666 1520,-1666 1626.25,-1772.25 C45.1
  Bottom Layer w20: 598,-1446 599.35,-1444.65 U4.3
  Bottom Layer w40: 406,-133 406,-803 406,-1076 497,-1167 598,-1268 598,-1446 598,-1624 640,-1666 843,-1666 1153,-1666 1368,-1666
  other v1: 372.36,-107.53 431.42,-107.53 372.36,-78 431.42,-78
VCC_5V: C1.2 C23.2 C24.1 C31.2 C35.2 P7.1 R5.1 R32.1 U1.2 U1.4 U2.3 U5.20 U6.7 U6.8 U7.5 U8.8 U9.5 | length 5182.7
  Top Layer w10: U6.7 U6.8 1743.33,-436.32 1744.45,-437.44 v1(1745.89,-436)
  Top Layer w15: 749.89,-365.89 750,-366 1165.89,-366 1392.89,-139 v1(1691.89,-139) ; v1(1745.89,-436) 1745.89,-488 1715.89,-518 1715.89,-746 1749.49,-779.6 v1(1749.49,-816.65) 1749.49,-864.49 1774.39,-889.39 U5.20
  Top Layer w20: 749.89,-365.89 U1.2 ; 750,-366 750,-423 860,-533 860,-670 835.35,-694.65 v1(756.06,-694.65) 672.24,-694.65 655.89,-711 655.89,-822 ; U9.5 688.54,-1091.65 655.89,-1059 655.89,-822 ; U7.5 656.24,-821.65 655.89,-822
  Top Layer w50: U2.3 492.44,-195.56 646,-42 737,-42 751,-56 ; U1.4@743.41,16.98 U1.4
  Bottom Layer w10: v1(756.06,-694.65) 756.06,-586.83 790.24,-552.65 R32.1 ; C23.2 v1(1749.49,-816.65) 1788,-855.17 1788,-946.11 1801.54,-959.65 R5.1
  Bottom Layer w15: C35.2 755.72,-695 v1(756.06,-694.65) ; v1(1691.89,-139) 1737.49,-139 C31.2 1804.89,-415 1783.89,-436 v1(1745.89,-436)
  Bottom Layer w80: P7.1 199,-65 290,26 715,26 754,-13 754,-97
  other v1: 708,-110.53 737.53,-110.53 767.06,-110.53 796.58,-110.53 708,-81 737.53,-81 767.06,-81 796.58,-81
pads on no net: P5.0@2012.58,-1001.92 P5.0@2149.2,-1001.92 P5.0@2149.2,-1285.39 P5.4 P5.FX P6.2 P8.1 P8.2 P9.1 P9.2 P9.3 P9.4 P9.6 P9.7 P9.8 U3.6 U3.10 U4.5 U5.22 U5.23 U5.24 U5.25 U5.27 U6.1 U6.2 U6.9 U6.10 U6.11 U6.12 U6.13 U6.14 U6.15 U6.16 U6.17 U6.18 U6.19 U6.20 U6.21 U6.22 U6.23 U6.24 U6.27 U6.28 U7.4 U9.4 U10.11 U10.12 U10.13 U11.5

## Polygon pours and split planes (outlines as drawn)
GND on Bottom Layer "Bottom Layer-GND" (solid, remove dead copper, pour order 6): -275,-2001 -186,-1912 -186,281 2503,281 2606,178 2437,9 2437,-1970
GND on Top Layer "Top Layer-GND" (solid, remove dead copper, pour order 8): -294,-2016 -294,312 -202,404 -114,316 2353,316 2353,-1714 2671,-2032

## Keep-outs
Keep-Out Layer:
  circle w5: c2125.98,-1771.65 r118.11
  circle w5: c0,-1771.65 r118.11
  circle w5: c0,0 r118.11
  circle w5: c2125.98,0 r118.11
  lines w5: -118.11,-1771.65 -118.11,0 ; 0,-1889.76 2125.98,-1889.76 ; 0,118.11 2125.98,118.11 ; 2244.09,-1771.65 2244.09,0

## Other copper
Top Layer:
  rectangle net VCC_5V: 732,-296 770,-133
  rectangle net VCC_5V: 685,-137 817,84
  rectangle net VCC_3V3: 337,-149 468,-44
  rectangle net VCC_3V3: 382,-295 422,-141
  rectangle net NetL2_2: 1989,-1100 2175,-1084
  rectangle net NetL2_2: 2088,-1100 2175,-1041
Bottom Layer:
  rectangle net VCC_5V: 685,-137 818,-48
  rectangle net VCC_3V3: 337,-148 468,-45
  rectangle net NetL2_2: 2088,-1100 2175,-1041

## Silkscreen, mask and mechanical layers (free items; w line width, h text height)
Top Overlay:
  text "3" at -949,415 h500
  text "2" at 2838,352 h500
  text "+" at 154,-76 h150 r270
  text "G" at 1993,-295 h60 r90
  text "R" at 1993,-342 h60 r90
  text "A" at 306,-372 h150 r270
  text "T" at 1995,-389 h60 r90
  text "+" at 1995,-437 h60 r90
  text "PMU" at 1921,-439 h100 r90
  text "B" at 299,-532 h150 r270
  text "G" at 296,-671 h150 r270
  text "H" at 1989,-738 h60 r90
  text "L" at 1985,-788 h60 r90
  text "1" at 138,-1263 h60 r270
  text "2" at 138,-1311 h60 r270
  text "3" at 136,-1359 h60 r270
  text "4" at 135,-1406 h60 r270
  text "P" at 1865,-1406 h100 r90
  text "G" at 1862,-1626 h100 r90
  text "1" at 2907,-2440 h500
  text "4" at -879,-2497 h500
Bottom Overlay:
  text "+" at -73,-294 h150 r270
  text "M100Ctrl_V4_20201229" at 1424,-330 h100
  text "A" at -68,-447 h150 r270
  text "B" at -81,-596 h150 r270
  text "G" at -84,-764 h150 r270
  text "P" at 2055,-1364 h100 r90
  text "G" at 2044,-1561 h100 r90
Mechanical 1:
  circle w5: c2125.98,-1771.65 r62.99
  circle w5: c0,-1771.65 r62.99
  circle w5: c0,0 r62.99
  circle w5: c2125.98,0 r62.99
  lines w5: -118.11,-1771.65 ccw(c0,-1771.65) 0,-1889.76 2125.98,-1889.76 ccw(c2125.98,-1771.65) 2244.09,-1771.65 2244.09,0 ccw(c2125.98,0) 2125.98,118.11 0,118.11 ccw(c0,0) -118.11,0 -118.11,-1771.65
Mechanical 15:
  lines w5: -19.68,-1771.65 19.69,-1771.65 ; -19.68,0 19.69,0 ; 0,-1791.34 0,-1751.97 ; 0,-19.69 0,19.68 ; 2106.3,-1771.65 2145.67,-1771.65 ; 2106.3,0 2145.67,0 ; 2125.98,-1791.34 2125.98,-1751.97 ; 2125.98,-19.69 2125.98,19.68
